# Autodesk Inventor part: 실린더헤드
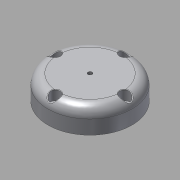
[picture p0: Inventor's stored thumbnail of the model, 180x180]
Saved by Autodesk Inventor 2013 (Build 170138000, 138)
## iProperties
Created: 2016-11
Part Number: 실린더헤드
Material: 알루미늄 6061
Document SubType Name: Modeling
Designer: mduedu
Density: 2.71 g/cm^3
Mass: 258.229 g
Surface Area: 216.959 cm^2
Volume: 95.2875 cm^3
Author: mduedu
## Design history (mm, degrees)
sketch "스케치1"
  geometry: C1 r 42 at (0, 0); 1 further point
  constraints: 1 centre point, 1 coincident
  dimensions: "d0" = 84 diameter of C1
extrude "돌출1" new body sketch "스케치1" distance "d1" = 24; taper "d2" = 0 deg
fillet "모깎기1" dims "d3" = 10
sketch "스케치2"
  geometry: C1 r 30 at (0, 0); 1 further point
  constraints: 1 centre point, 1 coincident
  dimensions: "d4" = 60 diameter of C1
extrude "돌출2" join sketch "스케치2" distance "d5" = 5; taper "d6" = 0 deg
sketch "스케치3"
  geometry: C1 r 25 at (0, 0); 1 further point
  constraints: 1 centre point, 1 coincident
  dimensions: "d7" = 50 diameter of C1
extrude "돌출3" cut sketch "스케치3" distance "d8" = 20; taper "d9" = 0 deg
hole "구멍1" diameter "d12" = 4.134; stored, may be unused: countersink angle "d16" = 90 deg, drill point angle "d18" = 118 deg; dims "d10" = 10, "d11" = 10, "d13" = 6, "d14" = 4, "d15" = 2, "d17" = 8
chamfer "모따기1" distance "d19" = 1; stored, may be unused: second distance "d20" = 2, angle "d21" = 45 deg
fillet "모깎기2" dims "d22" = 3
sketch "스케치4"
  geometry: C1 r 17.5 at (0, 0); 1 further point
  constraints: 1 centre point, 1 coincident
  dimensions: "d23" = 35 diameter of C1
extrude "돌출4" cut sketch "스케치4" distance "d24" = 2; taper "d25" = 0 deg
fillet "모깎기3" dims "d26" = 0.5
sketch "스케치5" dims "d32" = 70
  geometry: C1 r 5 at (0, 35); 3 further points
  constraints: 2 coincident, 2 vertical alignment, 1 centre point, 2 other
  dimensions: "d33" = 10 diameter of C1
extrude "돌출5" cut sketch "스케치5" distance "d34" = 10; taper "d35" = 0 deg
sketch "스케치6" dims "d39" = 70
  geometry: 6 further points
  constraints: 2 vertical alignment, 1 coincident, 7 other
  dimensions: "d42" = 360 deg dimension on point (0, -35) point (0, 0) (derived)
sketch "스케치7"
  geometry: 4 further points
  constraints: 4 other
hole "구멍2" sketch "스케치7" at (0, 70), (-35, 35), (35, 35), (0, 0) diameter "d44" = 5.5; stored, may be unused: countersink angle "d48" = 90 deg, drill point angle "d50" = 0 deg; dims "d45" = 6, "d46" = 4, "d47" = 2, "d49" = 8
fillet "모깎기4" dims "d51" = 0.5
chamfer "모따기2" distance "d54" = 5; stored, may be unused: second distance "d55" = 2, angle "d56" = 30 deg
node "솔리드1"
pattern_circular "원형 패턴1" dims angle "d37" = 360 deg
